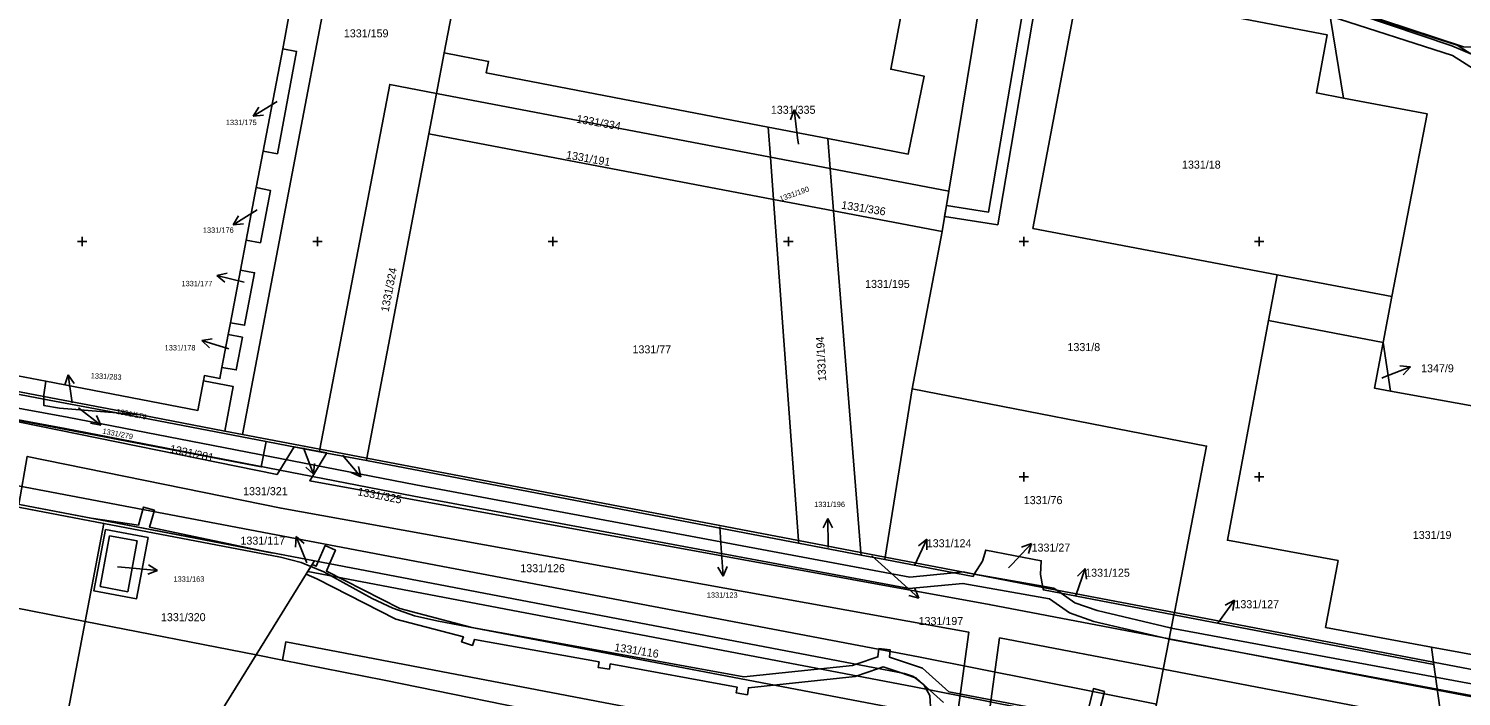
# Model space of a CAD drawing. Extents: x -601602 to -600882, y -1162594 to -1161950.
# Drawn here: x -601230.7 to -601078.5, y -1162198.3 to -1162127.4 of the extents above; entities that cross this region are included whole.
import ezdxf

# ---------------------------------------------------------------- set-up
doc = ezdxf.new("R2010")
doc.units = 0
for name, color, linetype in [('KN_Hranice parcel', 7, 'Continuous'), ('KN_Parcelní čísla', 7, 'Continuous'), ('KN_Pop  PČ popisy', 7, 'Continuous'), ('KN_Vnitřní kresba', 7, 'Continuous'), ('KN_Věcná břemena k části', 7, 'Continuous'), ('X_SOUR_KRIZKY_SEVER', 7, 'Continuous')]:
    doc.layers.add(name, color=color, linetype=linetype)

# ---------------------------------------------------------------- blocks, each defined once
blk = doc.blocks.new('1029_16')
at = {"layer": 'KN_Pop  PČ popisy'}
for p, q in [((0, 0), (2.99, -0.26)), ((2.99, -0.26), (2.04, 0.32)), ((2.99, -0.26), (1.95, -0.67))]:
    blk.add_line(p, q, dxfattribs=at)
blk = doc.blocks.new('1029_27')
at = {"layer": 'KN_Pop  PČ popisy'}
for p, q in [((0, 0), (1.76, 2.43)), ((1.76, 2.43), (0.77, 1.91)), ((1.76, 2.43), (1.58, 1.32))]:
    blk.add_line(p, q, dxfattribs=at)
blk = doc.blocks.new('1029_28')
at = {"layer": 'KN_Pop  PČ popisy'}
for p, q in [((0, 0), (1.27, 2.72)), ((1.27, 2.72), (0.39, 2.02)), ((1.27, 2.72), (1.3, 1.6))]:
    blk.add_line(p, q, dxfattribs=at)
blk = doc.blocks.new('1029_29')
at = {"layer": 'KN_Pop  PČ popisy'}
for p, q in [((0, 0), (0.98, 2.84)), ((0.98, 2.84), (0.18, 2.05)), ((0.98, 2.84), (1.12, 1.73))]:
    blk.add_line(p, q, dxfattribs=at)
blk = doc.blocks.new('1029_30')
at = {"layer": 'KN_Pop  PČ popisy'}
for p, q in [((0, 0), (0.21, -2.99)), ((0.21, -2.99), (-0.36, -2.03)), ((0.21, -2.99), (0.64, -1.96))]:
    blk.add_line(p, q, dxfattribs=at)
blk = doc.blocks.new('1029_35')
at = {"layer": 'KN_Pop  PČ popisy'}
for p, q in [((-1.12, 2.78), (-1.21, 1.67)), ((0, 0), (-1.12, 2.78)), ((-1.12, 2.78), (-0.29, 2.04))]:
    blk.add_line(p, q, dxfattribs=at)
blk = doc.blocks.new('1029_46')
at = {"layer": 'KN_Pop  PČ popisy'}
for p, q in [((0, 0), (2.8, 1.08)), ((2.8, 1.08), (1.69, 1.18)), ((2.8, 1.08), (2.05, 0.25))]:
    blk.add_line(p, q, dxfattribs=at)
blk = doc.blocks.new('1029_51')
at = {"layer": 'KN_Pop  PČ popisy'}
for p, q in [((0, 0), (1.93, -2.3)), ((1.93, -2.3), (1.67, -1.21)), ((1.93, -2.3), (0.9, -1.85))]:
    blk.add_line(p, q, dxfattribs=at)
blk = doc.blocks.new('1029_75')
at = {"layer": 'KN_Pop  PČ popisy'}
for p, q in [((0, 0), (-2.57, -1.55)), ((-2.57, -1.55), (-1.97, -0.6)), ((-2.57, -1.55), (-1.46, -1.46))]:
    blk.add_line(p, q, dxfattribs=at)
blk = doc.blocks.new('1029_76')
at = {"layer": 'KN_Pop  PČ popisy'}
for p, q in [((0, 0), (-2.54, -1.59)), ((-2.54, -1.59), (-1.96, -0.64)), ((-2.54, -1.59), (-1.43, -1.48))]:
    blk.add_line(p, q, dxfattribs=at)
blk = doc.blocks.new('1029_77')
at = {"layer": 'KN_Pop  PČ popisy'}
for p, q in [((-2.91, 0.73), (-1.82, 0.97)), ((0, 0), (-2.91, 0.73)), ((-2.91, 0.73), (-2.06, 0))]:
    blk.add_line(p, q, dxfattribs=at)
blk = doc.blocks.new('1029_78')
at = {"layer": 'KN_Pop  PČ popisy'}
for p, q in [((-2.87, 0.88), (-1.77, 1.06)), ((0, 0), (-2.87, 0.88)), ((-2.87, 0.88), (-2.06, 0.11))]:
    blk.add_line(p, q, dxfattribs=at)
blk = doc.blocks.new('1029_79')
at = {"layer": 'KN_Pop  PČ popisy'}
for p, q in [((0, 0), (2.36, -1.85)), ((2.36, -1.85), (1.88, -0.84)), ((2.36, -1.85), (1.27, -1.63))]:
    blk.add_line(p, q, dxfattribs=at)
blk = doc.blocks.new('1029_80')
at = {"layer": 'KN_Pop  PČ popisy'}
for p, q in [((-0.42, 2.97), (-0.77, 1.91)), ((0, 0), (-0.42, 2.97)), ((-0.42, 2.97), (0.22, 2.05))]:
    blk.add_line(p, q, dxfattribs=at)
blk = doc.blocks.new('1029_15')
at = {"layer": 'KN_Pop  PČ popisy'}
for p, q in [((0, 0), (2.05, 2.2)), ((2.05, 2.2), (1, 1.8)), ((2.05, 2.2), (1.73, 1.12))]:
    blk.add_line(p, q, dxfattribs=at)
blk = doc.blocks.new('1029_18')
at = {"layer": 'KN_Pop  PČ popisy'}
for p, q in [((-0.05, 3), (-0.54, 1.99)), ((0, 0), (-0.05, 3)), ((-0.05, 3), (0.47, 2.01))]:
    blk.add_line(p, q, dxfattribs=at)
blk = doc.blocks.new('1029_90')
at = {"layer": 'KN_Pop  PČ popisy'}
for p, q in [((0, 0), (2.23, -2.01)), ((2.23, -2.01), (1.82, -0.97)), ((2.23, -2.01), (1.15, -1.71))]:
    blk.add_line(p, q, dxfattribs=at)
blk = doc.blocks.new('1029_92')
at = {"layer": 'KN_Pop  PČ popisy'}
for p, q in [((0, 0), (1.07, -2.8)), ((1.07, -2.8), (0.25, -2.05)), ((1.07, -2.8), (1.18, -1.69))]:
    blk.add_line(p, q, dxfattribs=at)
blk = doc.blocks.new('1029_96')
at = {"layer": 'KN_Pop  PČ popisy'}
for p, q in [((-0.37, 2.98), (-0.74, 1.92)), ((0, 0), (-0.37, 2.98)), ((-0.37, 2.98), (0.25, 2.05))]:
    blk.add_line(p, q, dxfattribs=at)

msp = doc.modelspace()

# ---------------------------------------------------------------- linework, layer by layer
at = {"layer": 'KN_Hranice parcel'}
for p, q in [((-601127.79, -1162113.37), (-601132.96, -1162144.65)), ((-601203.69, -1162129.53), (-601202.96, -1162125.69)), ((-601091.03, -1162134.77), (-601092.67, -1162124.81)), ((-601205.76, -1162140.42), (-601203.69, -1162129.53)), ((-601187.37, -1162134.27), (-601186.54, -1162129.97)), ((-601187.37, -1162134.27), (-601188.19, -1162138.56)), ((-601151.91, -1162141.04), (-601187.37, -1162134.27)), ((-601152.14, -1162137.85), (-601145.82, -1162139.06)), ((-601151.91, -1162141.04), (-601152.14, -1162137.85)), ((-601188.19, -1162138.56), (-601194.76, -1162173.01)), ((-601151.58, -1162145.54), (-601188.19, -1162138.56)), ((-601145.82, -1162139.06), (-601145.56, -1162142.25)), ((-601206.5, -1162144.28), (-601205.76, -1162140.42)), ((-601151.91, -1162141.04), (-601151.58, -1162145.54)), ((-601145.56, -1162142.25), (-601151.91, -1162141.04)), ((-601145.56, -1162142.25), (-601132.96, -1162144.65)), ((-601145.2, -1162146.75), (-601145.56, -1162142.25)), ((-601207.56, -1162149.86), (-601206.5, -1162144.28)), ((-601151.58, -1162145.54), (-601145.2, -1162146.75)), ((-601148.93, -1162181.77), (-601151.58, -1162145.54)), ((-601132.96, -1162144.65), (-601133.67, -1162148.95)), ((-601142.29, -1162183.04), (-601145.2, -1162146.75)), ((-601133.67, -1162148.95), (-601145.2, -1162146.75)), ((-601208.17, -1162153.04), (-601207.56, -1162149.86)), ((-601133.67, -1162148.95), (-601136.85, -1162165.65)), ((-601209.23, -1162158.62), (-601208.17, -1162153.04)), ((-601209.47, -1162159.88), (-601209.23, -1162158.62)), ((-601099.02, -1162158.39), (-601086.84, -1162160.74)), ((-601210.14, -1162163.37), (-601209.47, -1162159.88)), ((-601086.05, -1162165.88), (-601086.84, -1162160.74)), ((-601234.56, -1162163.76), (-601228.86, -1162164.84)), ((-601229.06, -1162166.73), (-601235.08, -1162165.58)), ((-601235, -1162165.32), (-601229.07, -1162166.45)), ((-601136.85, -1162165.65), (-601139.73, -1162183.53)), ((-601229.07, -1162166.45), (-601229.06, -1162166.73)), ((-601229.07, -1162166.45), (-601218.78, -1162168.42)), ((-601221.31, -1162168.21), (-601229.06, -1162166.73)), ((-601205.45, -1162171.24), (-601221.31, -1162168.21)), ((-601221.31, -1162168.21), (-601218.78, -1162168.42)), ((-601218.78, -1162168.42), (-601209.84, -1162170.13)), ((-601209.84, -1162170.13), (-601207.97, -1162170.48)), ((-601207.97, -1162170.48), (-601199.75, -1162172.05)), ((-601199.8, -1162172.32), (-601205.45, -1162171.24)), ((-601199.8, -1162172.32), (-601199.75, -1162172.05)), ((-601194.81, -1162173.27), (-601199.8, -1162172.32)), ((-601199.75, -1162172.05), (-601194.76, -1162173.01)), ((-601194.76, -1162173.01), (-601194.81, -1162173.27)), ((-601194.81, -1162173.27), (-601148.91, -1162182.03)), ((-601194.76, -1162173.01), (-601148.93, -1162181.77)), ((-601244.84, -1162175.42), (-601200.33, -1162183.92)), ((-601224.66, -1162190.35), (-601222.67, -1162179.95)), ((-601148.91, -1162182.03), (-601148.93, -1162181.77)), ((-601148.93, -1162181.77), (-601142.29, -1162183.04)), ((-601142.27, -1162183.3), (-601148.91, -1162182.03)), ((-601200.33, -1162183.92), (-601200.7, -1162184.52)), ((-601142.27, -1162183.3), (-601142.29, -1162183.04)), ((-601142.29, -1162183.04), (-601139.73, -1162183.53)), ((-601139.77, -1162183.78), (-601142.27, -1162183.3)), ((-601139.73, -1162183.53), (-601139.77, -1162183.78)), ((-601139.73, -1162183.53), (-601130.25, -1162185.34)), ((-601200.7, -1162184.52), (-601206.52, -1162193.91)), ((-601130.25, -1162185.34), (-601122.96, -1162186.73)), ((-601224.66, -1162190.35), (-601245.33, -1162186.3)), ((-601122.96, -1162186.73), (-601109.01, -1162189.4)), ((-601111.25, -1162200.9), (-601109.06, -1162189.64)), ((-601109.01, -1162189.4), (-601109.06, -1162189.64)), ((-601109.06, -1162189.64), (-601081.46, -1162194.91)), ((-601081.49, -1162194.66), (-601109.01, -1162189.4)), ((-601233.71, -1162237.75), (-601224.66, -1162190.35)), ((-601206.52, -1162193.91), (-601224.66, -1162190.35)), ((-601206.52, -1162193.91), (-601216.98, -1162210.78)), ((-601206.52, -1162193.91), (-601203.73, -1162194.46)), ((-601081.71, -1162193.07), (-601066.62, -1162195.86)), ((-601081.49, -1162194.66), (-601081.71, -1162193.07)), ((-601081.46, -1162194.91), (-601081.49, -1162194.66)), ((-601080.82, -1162199.52), (-601081.46, -1162194.91))]:
    msp.add_line(p, q, dxfattribs=at)
for points in [[(-601194.38, -1162110.21), (-601196.29, -1162119.87), (-601198.26, -1162119.49), (-601207.97, -1162170.48)], [(-601194.38, -1162110.21), (-601183.15, -1162112.34), (-601186.54, -1162129.97)], [(-601091.03, -1162134.77), (-601093.93, -1162134.22), (-601092.77, -1162128.06), (-601119.19, -1162123), (-601124.02, -1162148.61), (-601098.1, -1162153.53), (-601099.02, -1162158.39)], [(-601145.82, -1162139.06), (-601137.26, -1162140.71), (-601135.56, -1162132.45), (-601139.12, -1162131.71), (-601138.01, -1162125.88), (-601146.98, -1162124.15)], [(-601092.71, -1162124.57), (-601078.32, -1162129.32), (-601064.66, -1162129.53)], [(-601066.62, -1162195.86), (-601064.16, -1162196.24), (-601064.09, -1162196.91), (-601063.85, -1162197.53), (-601063.36, -1162198.16), (-601062.35, -1162197.17), (-601061.34, -1162195.81), (-601060.57, -1162194.3), (-601060.06, -1162192.69), (-601056.32, -1162172.01), (-601055.73, -1162164.01), (-601056.42, -1162157.43), (-601059.89, -1162147.59), (-601061.76, -1162144.68), (-601064.91, -1162140.6), (-601068.2, -1162136.98), (-601070.82, -1162134.6), (-601075.02, -1162131.43), (-601077.22, -1162130.21), (-601079.54, -1162129.23), (-601092.67, -1162124.81)], [(-601203.69, -1162129.53), (-601202.22, -1162129.81), (-601204.26, -1162140.69), (-601205.76, -1162140.42)], [(-601186.54, -1162129.97), (-601181.83, -1162130.88), (-601182.07, -1162132.09), (-601152.14, -1162137.85)], [(-601199.75, -1162172.05), (-601192.33, -1162133.32), (-601187.37, -1162134.27)], [(-601086.84, -1162160.74), (-601085.9, -1162155.85), (-601082.16, -1162136.45), (-601091.03, -1162134.77)], [(-601206.5, -1162144.28), (-601205, -1162144.57), (-601206.06, -1162150.14), (-601207.56, -1162149.86)], [(-601208.17, -1162153.04), (-601206.67, -1162153.32), (-601207.74, -1162158.9), (-601209.23, -1162158.62)], [(-601099.02, -1162158.39), (-601103.38, -1162181.72), (-601091.63, -1162183.89), (-601092.95, -1162190.99), (-601081.71, -1162193.07)], [(-601209.47, -1162159.88), (-601207.97, -1162160.16), (-601208.62, -1162163.63), (-601210.14, -1162163.37)], [(-601086.05, -1162165.88), (-601087.77, -1162165.57), (-601086.84, -1162160.74)], [(-601212.1, -1162164.79), (-601212, -1162164.24), (-601210.36, -1162164.55), (-601210.14, -1162163.37)], [(-601228.86, -1162164.84), (-601229.07, -1162166.29), (-601229.07, -1162166.45)], [(-601228.86, -1162164.84), (-601212.7, -1162167.93), (-601212.1, -1162164.79)], [(-601212.1, -1162164.79), (-601208.96, -1162165.39), (-601209.84, -1162170.13)], [(-601109.01, -1162189.4), (-601105.58, -1162171.72), (-601136.85, -1162165.65)], [(-601205.45, -1162171.24), (-601205.97, -1162173.94), (-601243.26, -1162166.8), (-601247.21, -1162166.04)], [(-601229.06, -1162166.73), (-601229.04, -1162167.43), (-601227.39, -1162167.7), (-601221.31, -1162168.21)], [(-601066.62, -1162195.86), (-601065.25, -1162188.75), (-601061.68, -1162170.28), (-601086.05, -1162165.88)], [(-601222.67, -1162179.95), (-601237.9, -1162177.04), (-601244.89, -1162175.71)], [(-601222.51, -1162180.6), (-601223.74, -1162187.1), (-601219.2, -1162187.94), (-601217.99, -1162181.45), (-601222.51, -1162180.6)], [(-601222.67, -1162179.95), (-601203.91, -1162183.53), (-601201.74, -1162184.1), (-601200.7, -1162184.52)], [(-601132.64, -1162200.41), (-601134.86, -1162199.99), (-601134.98, -1162198.21), (-601135.62, -1162197.08), (-601136.72, -1162196.21), (-601137.65, -1162195.89), (-601200.33, -1162183.92)], [(-601139.77, -1162183.78), (-601130.39, -1162185.57), (-601130.25, -1162185.34)], [(-601122.96, -1162186.73), (-601123.24, -1162185.35), (-601123.14, -1162183.9), (-601129.03, -1162182.77), (-601129.38, -1162183.93), (-601130.25, -1162185.34)], [(-601132.7, -1162200.68), (-601184.93, -1162190.74), (-601187.33, -1162190.28), (-601189.7, -1162189.74), (-601192.01, -1162188.95), (-601194.21, -1162187.91), (-601199.31, -1162185.07), (-601200.7, -1162184.52)], [(-601122.96, -1162186.73), (-601122.91, -1162187), (-601109.06, -1162189.64)], [(-601203.73, -1162194.46), (-601203.36, -1162192.53), (-601137.37, -1162205.1), (-601138.11, -1162208.81)], [(-601203.73, -1162194.46), (-601192.92, -1162196.58), (-601152.65, -1162204.8), (-601147.15, -1162206.14)], [(-601081.49, -1162194.66), (-601068.33, -1162197.18), (-601067.54, -1162197), (-601066.91, -1162196.47), (-601066.62, -1162195.86)]]:
    msp.add_lwpolyline(points, dxfattribs=at)
at = {"layer": 'KN_Pop  PČ popisy'}
for p, q in [((-601148.93, -1162139.66), (-601149.02, -1162139)), ((-601086.99, -1162164.5), (-601086.75, -1162164.4)), ((-601157.28, -1162180.3), (-601157.13, -1162182.55)), ((-601145.77, -1162182.49), (-601145.77, -1162182.4)), ((-601141.12, -1162183.38), (-601138.37, -1162185.87)), ((-601221.25, -1162184.55), (-601219.98, -1162184.67)), ((-601126.61, -1162184.66), (-601126.23, -1162184.26))]:
    msp.add_line(p, q, dxfattribs=at)
at = {"layer": 'KN_Vnitřní kresba'}
for p, q in [((-601098.1, -1162153.53), (-601085.9, -1162155.85)), ((-601223.09, -1162186.64), (-601222.07, -1162181.24)), ((-601222.07, -1162181.24), (-601219.14, -1162181.8)), ((-601219.14, -1162181.8), (-601220.14, -1162187.2)), ((-601220.14, -1162187.2), (-601223.09, -1162186.64))]:
    msp.add_line(p, q, dxfattribs=at)
at = {"layer": 'KN_Věcná břemena k části'}
for points in [[(-601071.86, -1162133.64), (-601078.97, -1162129.14), (-601092.68, -1162124.75), (-601119.48, -1162116.16), (-601121.32, -1162115.94), (-601122.8, -1162116.34), (-601123.74, -1162118.12), (-601124.16, -1162119.88), (-601128.74, -1162146.87), (-601133.21, -1162146.17), (-601133.4, -1162147.34), (-601127.76, -1162148.23), (-601122.98, -1162120.12), (-601122.6, -1162118.54), (-601121.98, -1162117.36), (-601121.24, -1162117.16), (-601119.74, -1162117.34), (-601092.46, -1162126.08), (-601079.49, -1162130.24), (-601072.6, -1162134.6)], [(-601110.9, -1162199.12), (-601136.18, -1162194.12), (-601244.5, -1162173.54), (-601247.63, -1162172.94), (-601245.85, -1162163.52), (-601246.7, -1162163.36), (-601247.14, -1162165.72), (-601249.11, -1162174.61), (-601244.84, -1162175.42), (-601200.33, -1162183.92), (-601201.03, -1162185.05), (-601136.8, -1162197.26), (-601122.85, -1162200.02)], [(-601071.33, -1162198.12), (-601081.27, -1162196.27), (-601109.33, -1162191.05), (-601109.44, -1162191.03), (-601117.21, -1162189.2), (-601119.57, -1162188.37), (-601121.04, -1162187.36), (-601121.82, -1162186.82), (-601122.99, -1162186.61), (-601130.23, -1162185.31), (-601131.42, -1162185.09), (-601132.41, -1162185.19), (-601137.11, -1162185.64), (-601189.54, -1162175.85), (-601226.58, -1162168.67), (-601243.05, -1162165.63)], [(-601064.31, -1162200.86), (-601081.08, -1162197.65), (-601109.56, -1162192.2), (-601128.66, -1162188.54), (-601200.82, -1162175.41), (-601199.01, -1162172.46), (-601202.48, -1162171.8), (-601204.29, -1162174.75), (-601231.79, -1162169.15), (-601243.26, -1162166.79), (-601243.86, -1162170.07), (-601234.04, -1162172.11), (-601234.97, -1162177.31), (-601231.73, -1162177.92), (-601230.82, -1162172.83), (-601203.86, -1162178.32), (-601130.82, -1162191.5), (-601132.08, -1162200.52)], [(-601243.26, -1162166.81), (-601226.8, -1162169.85), (-601189.76, -1162177.03), (-601137.17, -1162186.86), (-601131.46, -1162186.31), (-601122.28, -1162187.96), (-601120.13, -1162189.45), (-601117.55, -1162190.36), (-601109.68, -1162192.21), (-601109.56, -1162192.23), (-601081.1, -1162197.53), (-601071.41, -1162199.33)], [(-601122.53, -1162199.81), (-601132.97, -1162197.83), (-601135.76, -1162195.31), (-601139.27, -1162194.14), (-601139.19, -1162193.35), (-601140.39, -1162193.23), (-601140.48, -1162194.11), (-601142.81, -1162194.9), (-601143.18, -1162195.03), (-601154.72, -1162196.23), (-601169.32, -1162193.57), (-601183.61, -1162190.98), (-601191.26, -1162188.97), (-601199.04, -1162185.01), (-601198.71, -1162184.23), (-601198.09, -1162182.77), (-601199.2, -1162182.3), (-601199.92, -1162184), (-601200.13, -1162184.49), (-601200.56, -1162184.3), (-601201.2, -1162185.32), (-601200.07, -1162185.83), (-601191.68, -1162190.09), (-601184.51, -1162191.99), (-601184.69, -1162192.52), (-601183.55, -1162192.9), (-601183.34, -1162192.26), (-601170.1, -1162194.65), (-601170.18, -1162195.25), (-601168.98, -1162195.4), (-601168.91, -1162194.86), (-601155.43, -1162197.33), (-601155.53, -1162197.93), (-601154.35, -1162198.13), (-601154.23, -1162197.39), (-601142.92, -1162196.21), (-601140.44, -1162195.36), (-601139.92, -1162195.18), (-601138.02, -1162195.82), (-601136.62, -1162196.29), (-601136.38, -1162196.37), (-601133.53, -1162198.95)], [(-601128.83, -1162201.14), (-601127.57, -1162192.1), (-601110.18, -1162195.43), (-601081.34, -1162200.95)], [(-601116.95, -1162199.85), (-601116.44, -1162197.77), (-601117.61, -1162197.48), (-601118.14, -1162199.63)]]:
    msp.add_lwpolyline(points, dxfattribs=at)
msp.add_lwpolyline([(-601204.72, -1162183.08), (-601217.83, -1162180.35), (-601217.31, -1162178.54), (-601218.46, -1162178.21), (-601219.01, -1162180.14), (-601224.04, -1162179.39)], close=True, dxfattribs=at)
at = {"layer": 'X_SOUR_KRIZKY_SEVER'}
for p, q in [((-601225.5, -1162150), (-601224.5, -1162150)), ((-601225, -1162150.5), (-601225, -1162149.5)), ((-601200.5, -1162150), (-601199.5, -1162150)), ((-601200, -1162150.5), (-601200, -1162149.5)), ((-601175.5, -1162150), (-601174.5, -1162150)), ((-601175, -1162150.5), (-601175, -1162149.5)), ((-601150.5, -1162150), (-601149.5, -1162150)), ((-601150, -1162150.5), (-601150, -1162149.5)), ((-601125.5, -1162150), (-601124.5, -1162150)), ((-601125, -1162150.5), (-601125, -1162149.5)), ((-601100.5, -1162150), (-601099.5, -1162150)), ((-601100, -1162150.5), (-601100, -1162149.5)), ((-601125, -1162175.5), (-601125, -1162174.5)), ((-601100, -1162175.5), (-601100, -1162174.5)), ((-601125.5, -1162175), (-601124.5, -1162175)), ((-601100.5, -1162175), (-601099.5, -1162175))]:
    msp.add_line(p, q, dxfattribs=at)

# ---------------------------------------------------------------- block references
at = {"layer": 'KN_Pop  PČ popisy'}
for name, p in [('1029_75', (-601204.27, -1162135.14)), ('1029_96', (-601149.02, -1162139)), ('1029_76', (-601206.41, -1162146.63)), ('1029_77', (-601207.77, -1162154.33)), ('1029_78', (-601209.41, -1162161.39)), ('1029_46', (-601086.75, -1162164.4)), ('1029_80', (-601226.06, -1162167.14)), ('1029_79', (-601225.36, -1162167.65)), ('1029_92', (-601201.5, -1162171.9)), ('1029_51', (-601197.33, -1162172.68)), ('1029_18', (-601145.77, -1162182.4)), ('1029_35', (-601201.14, -1162184.12)), ('1029_28', (-601136.58, -1162184.33)), ('1029_15', (-601126.23, -1162184.26)), ('1029_30', (-601157.13, -1162182.55)), ('1029_16', (-601219.98, -1162184.67)), ('1029_29', (-601119.46, -1162187.58)), ('1029_90', (-601138.37, -1162185.87)), ('1029_27', (-601104.39, -1162190.52))]:
    msp.add_blockref(name, p, dxfattribs=at)

# ---------------------------------------------------------------- texts
at = {"layer": 'KN_Parcelní čísla'}
for s, height, p in [('1331/159', 0.85, (-601197.2, -1162128.32)), ('1331/335', 0.85, (-601151.86, -1162136.44)), ('1331/175', 0.569, (-601209.73, -1162137.64)), ('1331/18', 0.85, (-601108.2, -1162142.26)), ('1331/176', 0.569, (-601212.17, -1162149.08)), ('1331/177', 0.569, (-601214.44, -1162154.75)), ('1331/195', 0.85, (-601141.85, -1162154.93)), ('1331/178', 0.569, (-601216.23, -1162161.57)), ('1331/77', 0.85, (-601166.55, -1162161.88)), ('1331/8', 0.85, (-601120.36, -1162161.64)), ('1347/9', 0.85, (-601082.81, -1162163.89)), ('1331/321', 0.85, (-601207.9, -1162176.94)), ('1331/196', 0.569, (-601147.26, -1162178.2)), ('1331/76', 0.85, (-601125, -1162177.89)), ('1331/19', 0.85, (-601083.69, -1162181.59)), ('1331/117', 0.85, (-601208.18, -1162182.19)), ('1331/124', 0.85, (-601135.3, -1162182.47)), ('1331/27', 0.85, (-601124.17, -1162182.93)), ('1331/126', 0.85, (-601178.46, -1162185.12)), ('1331/125', 0.85, (-601118.48, -1162185.6)), ('1331/163', 0.569, (-601215.29, -1162186.13)), ('1331/123', 0.569, (-601158.66, -1162187.83)), ('1331/127', 0.85, (-601102.63, -1162188.94)), ('1331/320', 0.85, (-601216.62, -1162190.32)), ('1331/197', 0.85, (-601136.17, -1162190.73))]:
    msp.add_text(s, height=height, dxfattribs=at).set_placement(p)
for s, height, rotation, p in [('1331/334', 0.85, 350, (-601172.55, -1162137.37)), ('1331/191', 0.85, 350, (-601173.65, -1162141.18)), ('1331/190', 0.57, 20, (-601150.82, -1162145.77)), ('1331/336', 0.85, 351, (-601144.42, -1162146.51)), ('1331/324', 0.85, 79, (-601192.45, -1162157.53)), ('1331/194', 0.85, 93, (-601145.97, -1162164.81)), ('1331/283', 0.569, 357, (-601224.09, -1162164.53)), ('1331/179', 0.569, 349, (-601221.41, -1162168.29)), ('1331/279', 0.569, 349, (-601222.87, -1162170.39)), ('1331/281', 0.85, 348, (-601215.75, -1162172.4)), ('1331/325', 0.85, 349, (-601195.8, -1162176.94)), ('1331/116', 0.85, 351, (-601168.52, -1162193.48))]:
    msp.add_text(s, height=height, rotation=rotation, dxfattribs=at).set_placement(p)

doc.saveas('drawing.dxf')
